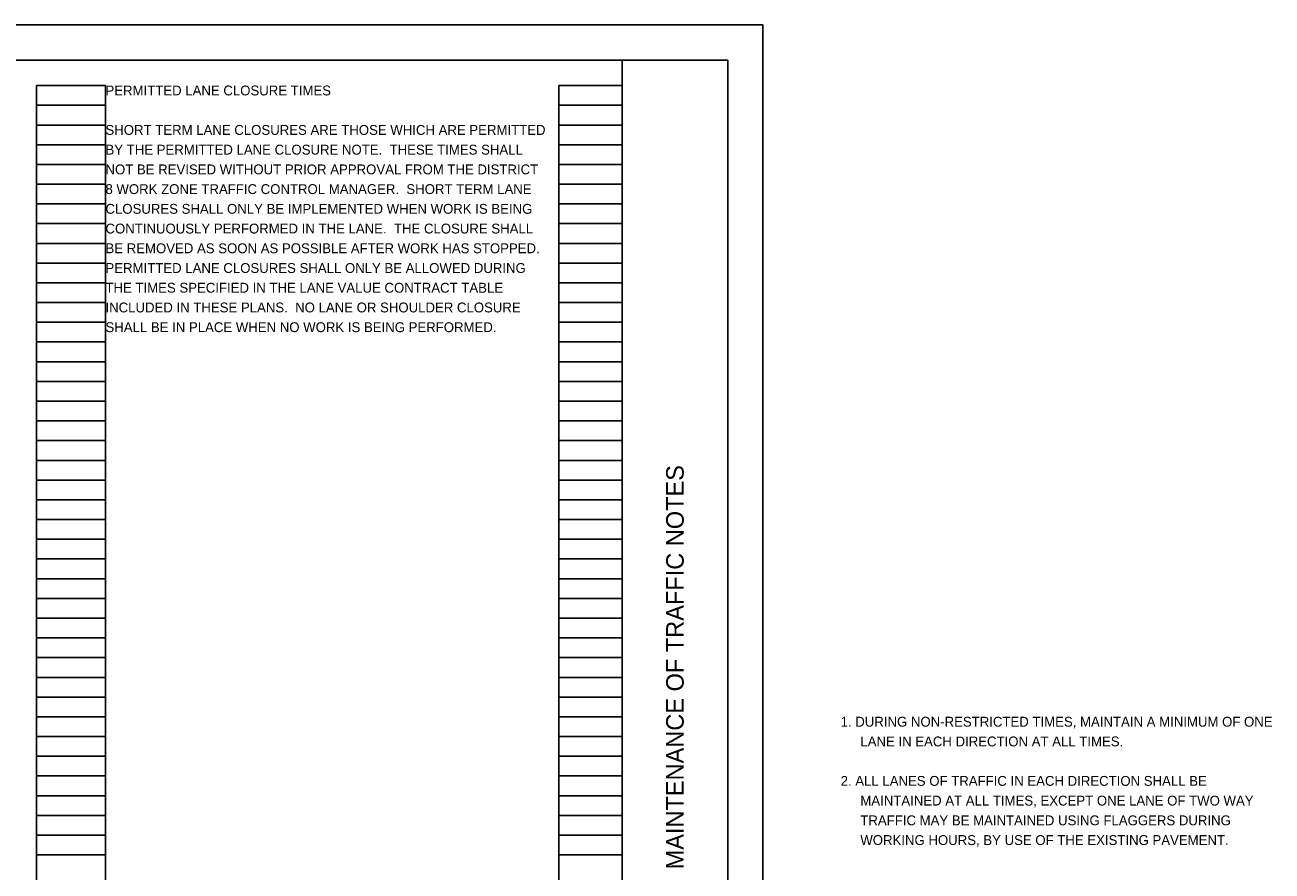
# Model space of a CAD drawing. Extents: x 0 to 41.4, y 0 to 22.
# Drawn here: x 23.52 to 41.23, y 9.99 to 22 of the extents above; entities that cross this region are included whole.
import ezdxf

# ---------------------------------------------------------------- set-up
doc = ezdxf.new("R2010")
doc.units = 0
for name, color, linetype in [('SH_Border', 7, 'Continuous'), ('SH_Cut_Line', 7, 'Continuous'), ('SH_Data', 7, 'Continuous'), ('SH_Text', 7, 'Continuous')]:
    doc.layers.add(name, color=color, linetype=linetype)

msp = doc.modelspace()

# ---------------------------------------------------------------- linework, layer by layer
at = {"layer": 'SH_Border'}
msp.add_line((32, 0.5), (32, 21.5), dxfattribs=at)
msp.add_lwpolyline([(1.5, 21.5), (33.5, 21.5), (33.5, 0.5), (1.5, 0.5)], close=True, dxfattribs=at)
at = {"layer": 'SH_Cut_Line'}
msp.add_lwpolyline([(0, 0), (34, 0), (34, 22), (0, 22)], close=True, dxfattribs=at)
at = {"layer": 'SH_Data'}
for p, q in [((23.68, 0.98), (23.68, 21.14)), ((23.68, 21.14), (24.66, 21.14)), ((24.66, 0.98), (24.66, 21.14)), ((31.1, 0.98), (31.1, 21.14)), ((31.1, 21.14), (32, 21.14)), ((32, 0.98), (32, 21.14)), ((23.68, 20.86), (24.66, 20.86)), ((31.1, 20.86), (32, 20.86)), ((23.68, 20.58), (24.66, 20.58)), ((31.1, 20.58), (32, 20.58)), ((23.68, 20.3), (24.66, 20.3)), ((31.1, 20.3), (32, 20.3)), ((23.68, 20.02), (24.66, 20.02)), ((31.1, 20.02), (32, 20.02)), ((23.68, 19.74), (24.66, 19.74)), ((31.1, 19.74), (32, 19.74)), ((23.68, 19.46), (24.66, 19.46)), ((31.1, 19.46), (32, 19.46)), ((23.68, 19.18), (24.66, 19.18)), ((31.1, 19.18), (32, 19.18)), ((23.68, 18.9), (24.66, 18.9)), ((31.1, 18.9), (32, 18.9)), ((23.68, 18.62), (24.66, 18.62)), ((31.1, 18.62), (32, 18.62)), ((23.68, 18.34), (24.66, 18.34)), ((31.1, 18.34), (32, 18.34)), ((23.68, 18.06), (24.66, 18.06)), ((31.1, 18.06), (32, 18.06)), ((23.68, 17.78), (24.66, 17.78)), ((31.1, 17.78), (32, 17.78)), ((23.68, 17.5), (24.66, 17.5)), ((31.1, 17.5), (32, 17.5)), ((23.68, 17.22), (24.66, 17.22)), ((31.1, 17.22), (32, 17.22)), ((23.68, 16.94), (24.66, 16.94)), ((31.1, 16.94), (32, 16.94)), ((23.68, 16.66), (24.66, 16.66)), ((31.1, 16.66), (32, 16.66)), ((23.68, 16.38), (24.66, 16.38)), ((31.1, 16.38), (32, 16.38)), ((23.68, 16.1), (24.66, 16.1)), ((31.1, 16.1), (32, 16.1)), ((23.68, 15.82), (24.66, 15.82)), ((31.1, 15.82), (32, 15.82)), ((23.68, 15.54), (24.66, 15.54)), ((31.1, 15.54), (32, 15.54)), ((23.68, 15.26), (24.66, 15.26)), ((31.1, 15.26), (32, 15.26)), ((23.68, 14.98), (24.66, 14.98)), ((31.1, 14.98), (32, 14.98)), ((23.68, 14.7), (24.66, 14.7)), ((31.1, 14.7), (32, 14.7)), ((23.68, 14.42), (24.66, 14.42)), ((31.1, 14.42), (32, 14.42)), ((23.68, 14.14), (24.66, 14.14)), ((31.1, 14.14), (32, 14.14)), ((23.68, 13.86), (24.66, 13.86)), ((31.1, 13.86), (32, 13.86)), ((23.68, 13.58), (24.66, 13.58)), ((31.1, 13.58), (32, 13.58)), ((23.68, 13.3), (24.66, 13.3)), ((31.1, 13.3), (32, 13.3)), ((23.68, 13.02), (24.66, 13.02)), ((31.1, 13.02), (32, 13.02)), ((23.68, 12.74), (24.66, 12.74)), ((31.1, 12.74), (32, 12.74)), ((23.68, 12.46), (24.66, 12.46)), ((31.1, 12.46), (32, 12.46)), ((23.68, 12.18), (24.66, 12.18)), ((31.1, 12.18), (32, 12.18)), ((23.68, 11.9), (24.66, 11.9)), ((31.1, 11.9), (32, 11.9)), ((23.68, 11.62), (24.66, 11.62)), ((31.1, 11.62), (32, 11.62)), ((23.68, 11.34), (24.66, 11.34)), ((31.1, 11.34), (32, 11.34)), ((23.68, 11.06), (24.66, 11.06)), ((31.1, 11.06), (32, 11.06)), ((23.68, 10.78), (24.66, 10.78)), ((31.1, 10.78), (32, 10.78)), ((23.68, 10.5), (24.66, 10.5)), ((31.1, 10.5), (32, 10.5)), ((23.68, 10.22), (24.66, 10.22)), ((31.1, 10.22), (32, 10.22))]:
    msp.add_line(p, q, dxfattribs=at)

# ---------------------------------------------------------------- texts
msp.add_text('MAINTENANCE OF TRAFFIC NOTES', height=0.25, rotation=90, dxfattribs=at).set_placement((32.875, 10.014))
at = {"layer": 'SH_Text'}
for s, p in [('PERMITTED LANE CLOSURE TIMES ', (24.66, 21)), ('SHORT TERM LANE CLOSURES ARE THOSE WHICH ARE PERMITTED ', (24.66, 20.44)), ('BY THE PERMITTED LANE CLOSURE NOTE.  THESE TIMES SHALL ', (24.66, 20.16)), ('NOT BE REVISED WITHOUT PRIOR APPROVAL FROM THE DISTRICT ', (24.66, 19.88)), ('8 WORK ZONE TRAFFIC CONTROL MANAGER.  SHORT TERM LANE ', (24.66, 19.6)), ('CLOSURES SHALL ONLY BE IMPLEMENTED WHEN WORK IS BEING ', (24.66, 19.32)), ('CONTINUOUSLY PERFORMED IN THE LANE.  THE CLOSURE SHALL ', (24.66, 19.04)), ('BE REMOVED AS SOON AS POSSIBLE AFTER WORK HAS STOPPED.  ', (24.66, 18.76)), ('PERMITTED LANE CLOSURES SHALL ONLY BE ALLOWED DURING ', (24.66, 18.48)), ('THE TIMES SPECIFIED IN THE LANE VALUE CONTRACT TABLE ', (24.66, 18.2)), ('INCLUDED IN THESE PLANS.  NO LANE OR SHOULDER CLOSURE ', (24.66, 17.92)), ('SHALL BE IN PLACE WHEN NO WORK IS BEING PERFORMED. ', (24.66, 17.64)), ('1. DURING NON-RESTRICTED TIMES, MAINTAIN A MINIMUM OF ONE ', (35.104, 12.04)), ('LANE IN EACH DIRECTION AT ALL TIMES. ', (35.384, 11.76)), ('2. ALL LANES OF TRAFFIC IN EACH DIRECTION SHALL BE ', (35.104, 11.2)), ('MAINTAINED AT ALL TIMES, EXCEPT ONE LANE OF TWO WAY ', (35.384, 10.92)), ('TRAFFIC MAY BE MAINTAINED USING FLAGGERS DURING ', (35.384, 10.64)), ('WORKING HOURS, BY USE OF THE EXISTING PAVEMENT.  ', (35.384, 10.36))]:
    msp.add_text(s, height=0.14, dxfattribs=at).set_placement(p)

doc.saveas('drawing.dxf')
